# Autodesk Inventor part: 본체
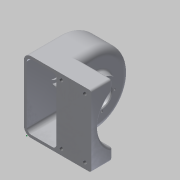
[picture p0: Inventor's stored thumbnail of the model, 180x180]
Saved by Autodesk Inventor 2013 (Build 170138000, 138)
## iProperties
Created: 2015-02
Part Number: 본체
Material: 알루미늄 6061
Document SubType Name: Modeling
Designer: Administrator
Density: 1 g/cm^3
Author: Administrator
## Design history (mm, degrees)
sketch "스케치1"
  geometry: L1 (0, 0)-(95, 0); L2 (95, 0)-(95, 100); L3 (95, 100)-(0, 100); L4 (0, 100)-(0, 0); 4 further points
  constraints: 8 end point, 2 parallel, 1 horizontal, 1 perpendicular
  dimensions: "d0" = 100 distance of L1.end L2.end; "d2" = 95 distance of L2.end L3.end; "d3" = 9 distance from line of L4 point (9, 91.75); "d4" = 33 distance of point (9, 91.75) point (42, 91.75); "d5" = 9 distance from line of L4 point (9, 8.25); "d6" = 33 distance of point (9, 8.25) point (42, 8.25); "d7" = 83.5 distance of point (9, 91.75) point (9, 8.25); "d8" = 8.25 distance from line of L3 point (9, 91.75); "d9" = 8.25 distance from line of L1 point (42, 8.25); "d10" = 8.25 distance from line of L3 point (42, 91.75)
extrude "돌출1" new body sketch "스케치1" distance "d11" = 30; taper "d12" = 0 deg
node "작업 평면1"
sketch "스케치2"
  geometry: L1 (0, 30)-(100, 30) reference; L2 (0, 0)-(0, 30) reference; L3 (100, 0)-(100, 30) reference; L4 (0, 0)-(100, 0) reference; C1 r 50 at (50, 50); C2 r 20 at (50, 50); 1 further point
  constraints: 2 centre point, 1 coincident, 1 midpoint, 1 vertical alignment
  dimensions: "d14" = 100 diameter of C1; "d16" = 50 distance from line of L4 C1.centre; "d17" = 40 diameter of C2
extrude "돌출2" join sketch "스케치2" distance "d18" = 50; taper "d19" = 0 deg
extrude "돌출3" join sketch "스케치2" distance "d20" = 9; taper "d21" = 0 deg
node "작업 평면2"
sketch "스케치3"
  geometry: L1 (-45, 4.174)-(-45, 95.826) reference; L2 (-45, 50)-(-35, 50); L3 (-35, 50)-(-35, 73.237); L4 (-35, 73.237)-(-45, 75); 1 further point
  constraints: 6 end point, 2 perpendicular, 1 midpoint, 1 point on line
  dimensions: "d23" = 50 diameter of L4.end L2; "d25" = 100 deg angle of L1 L4; "d27" = 10 distance of L2.start L2.end
revolve "회전1" stored, may be unused: angle "d28" = 90 deg
sketch "스케치4"
  geometry: L1 (0, 30)-(4.174, 30) reference; L2 (0, 0)-(0, 30) reference; L3 (0, 30)-(0, 50); L4 (100, 0)-(100, 30) reference; L5 (95.826, 30)-(100, 30) reference; L6 (100, 30)-(100, 50); L7 (100, 30)-(0, 30); A1 r 50 centre (50, 50) between (4.174, 30) and (0, 50) reference; A2 r 50 centre (50, 50) between (0, 50) and (100, 50); A3 r 50 centre (50, 50) between (95.826, 30) and (4.174, 30) reference
  constraints: 6 end point, 4 point on circle, 2 tangent, 1 centre point, 1 coincident, 1 perpendicular
extrude "돌출4" join sketch "스케치4" distance "d29" = 50; taper "d30" = 0 deg
node "작업 평면3"
sketch "스케치5"
  geometry: C1 r 40 at (50, 50); A1 r 50 centre (50, 50) between (100, 50) and (0, 50) reference; 1 further point
  constraints: 1 centre point, 1 coincident
extrude "돌출5" cut sketch "스케치5" distance "d32" = 45; taper "d33" = 0 deg
revolve "회전2" stored, may be unused: angle "d34" = 90 deg
node "작업 평면4"
sketch "스케치6"
  geometry: L1 (0, 0)-(0, 30) reference; L2 (100, 0)-(0, 0) reference; L3 (0, 30)-(0, 50) reference; L4 (100, 50)-(100, 30) reference; L5 (100, 0)-(100, 30) reference; L6 (4, 4)-(96, 4); L7 (4, 4)-(4, 50); L8 (96, 4)-(96, 50); A1 r 50 centre (50, 50) between (100, 50) and (0, 50) reference; A2 r 46 centre (50, 50) between (96, 50) and (4, 50)
  constraints: 6 end point, 2 perpendicular, 2 point on circle, 1 centre point, 1 coincident, 1 parallel
  dimensions: "d35" = 4 distance between parallel lines of L2 L6; "d36" = 4 distance between parallel lines of L1 L7; "d37" = 4 distance between parallel lines of L5 L8; "d38" = 4 radial gap between concentric circles of A2 A1
extrude "돌출6" cut sketch "스케치6" stored distance "d39" = 42; taper "d40" = 0 deg
hole "구멍1" diameter "d43" = 28; stored, may be unused: countersink angle "d47" = 90 deg, drill point angle "d49" = 0 deg; dims "d41" = 10, "d42" = 10, "d44" = 6, "d45" = 4, "d46" = 2, "d48" = 10
hole "구멍2" diameter "d52" = 20; stored, may be unused: countersink angle "d56" = 90 deg, drill point angle "d58" = 0 deg; dims "d50" = 10, "d51" = 10, "d53" = 6, "d54" = 4, "d55" = 2, "d57" = 4
sketch "스케치7"
  geometry: L1 (0, 0)-(-95, 0) reference; L2 (-95, 100)-(0, 100) reference; L3 (-95, 0)-(-95, 100) reference; L4 (-91, 96)-(-91, 4); L5 (-91, 4)-(-49, 4); L6 (-49, 4)-(-49, 96); L7 (-49, 96)-(-91, 96)
  constraints: 8 end point, 3 parallel, 1 perpendicular
  dimensions: "d59" = 4 distance between parallel lines of L1 L5; "d60" = 4 distance between parallel lines of L3 L4; "d61" = 4 distance between parallel lines of L2 L7; "d62" = 42 distance between parallel lines of L4 L6
extrude "돌출7" cut sketch "스케치7" distance "d63" = 10; taper "d64" = 0 deg
sketch "스케치8"
  geometry: A1 r 46 centre (-50, 50) between (-4, 50) and (-96, 50) reference; 2 further points
  constraints: 1 coincident
hole "구멍3" sketch "스케치8" diameter "d65" = 28; stored, may be unused: countersink angle "d69" = 90 deg, drill point angle "d71" = 0 deg; dims "d66" = 6, "d67" = 4, "d68" = 2, "d70" = 8
hole "구멍4" sketch "스케치8" diameter "d72" = 20; stored, may be unused: countersink angle "d76" = 90 deg, drill point angle "d78" = 0 deg; dims "d73" = 6, "d74" = 4, "d75" = 2, "d77" = 10
hole "구멍5" sketch "스케치1" diameter "d79" = 5.134; stored, may be unused: countersink angle "d83" = 90 deg, drill point angle "d85" = 118 deg; dims "d80" = 10, "d81" = 4, "d82" = 2, "d84" = 13
sketch "스케치9"
  geometry: L1 (0, 0)-(-18, 0); L2 (0, 0)-(0, 18); L3 (0, 0)-(18, 0); L4 (0, 0)-(0, -18); C1 r 23.237 at (0, 0) reference; A1 r 18 centre (0, 0) between (-18, 0) and (0, 18); 5 further points
  constraints: 8 end point, 5 coincident, 4 point on circle, 3 perpendicular, 1 centre point, 1 horizontal
  dimensions: "d86" = 36 diameter of A1
hole "구멍6" sketch "스케치9" at (0, 18), (-18, 0), (0, -18), (18, 0) diameter "d88" = 2.459; stored, may be unused: countersink angle "d92" = 90 deg, drill point angle "d94" = 118 deg; dims "d89" = 6, "d90" = 4, "d91" = 2, "d93" = 9
chamfer "모따기1" distance "d95" = 1; stored, may be unused: second distance "d96" = 2, angle "d97" = 45 deg
chamfer "모따기2" distance "d98" = 1; stored, may be unused: second distance "d99" = 2, angle "d100" = 45 deg
fillet "모깎기1" dims "d101" = 0.3
fillet "모깎기2" dims "d102" = 0.3
fillet "모깎기3" dims "d103" = 6
fillet "모깎기4" dims "d104" = 10
fillet "모깎기5" dims "d105" = 3
fillet "모깎기6" dims "d106" = 3
fillet "모깎기7" dims "d107" = 3
node "작업 평면5"
sketch "스케치10"
  geometry: L1 (0, 40)-(0, -40) reference; 3 further points
  constraints: 1 horizontal alignment, 1 midpoint, 1 other
  dimensions: "d108" = 25 distance from line of point (-25, 0) L1
feature "엠보싱1" sketch "스케치10" dims "d0" = 100, "d2" = 95, "d3" = 9, "d4" = 33, "d5" = 9, "d6" = 33, "d7" = 83.5, "d8" = 8.25, "d9" = 8.25, "d10" = 8.25, "d109" = 0.5, "d110" = 0
node "솔리드1"
other parameters: "d13" = 0, "d31" = 0
